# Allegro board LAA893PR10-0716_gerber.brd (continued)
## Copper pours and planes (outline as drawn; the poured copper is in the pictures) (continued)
PBATT+_C on IN2 (solid shape): 62.67,16.67 62.67,11.92 62.59,11.7 62.67,11.47 62.67,9.89 61.86,9.08 61.86,8.14 61.75,8.03 59.11,8.03 58.86,8.28 58.86,9.12 58.86,9.12 58.86,16.72 59.04,16.9 62.44,16.9
PWM1 on BOTTOM (solid shape): 100.06,58.87 100.06,58.65 100.18,58.53 100.5,58.53 100.66,58.37 100.66,57.54 100.6,57.48 99.84,57.48 99.77,57.55 99.77,57.93 99.29,58.41 99.29,58.85 99.42,58.98 99.95,58.98
REGCTL_PNP10 on TOP (solid shape): 252.45,86.34 252.45,86.24 252.52,85.85 252.9,85.76 252.91,85.76 253.13,85.76 253.18,85.71 254.11,85.71 254.17,85.64 254.17,85.53 254.12,85.48 253.09,85.48 253.07,85.45 253.03,85.45 252.94,85.36 251.73,85.36 251.34,84.98 250.43,84.98 250.23,85.17 250.23,86.5 250.49,86.76 252.03,86.76
RING2 on TOP (solid shape): 29.18,18.69 30.6,18.69 30.65,18.64 30.65,18.51 30.6,18.46 27.92,18.46 27.47,18.91 27.47,18.92 25.47,18.92 25.42,18.96 25.42,19.86 25.5,19.94 27.93,19.94
RING2_R on TOP (solid shape): 25.17,20 25.17,19.04 25,18.87 23.09,18.87 22.9,19.05 22.9,19.99 23.05,20.14 25.03,20.14
RING2_R on TOP (solid shape): 15.8,14.95 17.51,14.95 17.73,15.17 18.22,15.17 18.39,15 18.39,14.18 18.23,14.02 17.58,14.02 17.45,13.89 16.5,13.89 16.49,13.91 15.63,13.91 15.62,13.91 14.44,13.91 14.26,14.1 14.26,15.04 14.48,15.25 15.49,15.25
RING2_R on BOTTOM (solid shape): 18.63,15 18.63,14.63 19.09,14.17 20.05,14.17 20.28,13.95 20.28,13.18 20.05,12.95 18.43,12.95 17.61,13.77 17.61,14.96 17.83,15.18 18.45,15.18
RING2_R on IN1 (solid shape): 24.31,19.67 24.31,19.37 23.11,18.17 22.82,18.17 21.96,19.04 21.96,19.18 23.04,20.26 23.72,20.26
RING2_R on IN1 (solid shape): 4.7,15.47 4.7,14.83 5.08,14.45 13.7,14.45 14.41,15.16 14.98,15.16 15.16,14.99 15.16,14.3 14.55,13.69 3.11,13.69 2.79,14.01 2.79,15.4 3.11,15.72 4.44,15.72
RING2_R on IN1 (solid shape): 18.48,14.93 18.48,14.74 18.76,14.46 19.67,14.46 20.05,14.08 20.05,13.39 19.73,13.07 18.12,13.07 17.18,14.01 17.18,14.9 17.46,15.18 18.23,15.18
RING2_R on IN2 (solid shape): 4.7,15.47 4.7,14.83 5.08,14.45 13.73,14.45 14.41,15.14 14.72,15.14 14.86,14.99 14.86,14.05 14.5,13.69 3.11,13.69 2.79,14.01 2.79,15.4 3.11,15.72 4.44,15.72
SLEEVE on TOP (solid shape): 26.9,25.88 27.43,25.88 27.55,25.76 27.55,25.44 27.43,25.32 26.93,25.32 26.83,25.22 25.9,25.22 25.71,25.41 25.71,25.74 25.91,25.93 26.85,25.93
SLEEVE on TOP (solid shape): 25.22,18.43 25.22,17.98 25.44,17.77 27.12,17.77 27.13,17.75 27.55,17.75 27.56,17.77 27.63,17.77 28.2,18.33 29.7,18.33 29.75,18.28 30.59,18.28 30.65,18.22 30.65,18.12 30.6,18.06 29.64,18.06 29.26,17.68 28.75,17.68 28.07,16.99 24.01,16.99 23.91,17.09 23.91,18.47 24.06,18.62 25.03,18.62
SLEEVE on IN1 (solid shape): 25.97,19.52 25.97,18.31 25.38,17.73 24.31,17.73 24.03,18.01 24.03,18.66 25.08,19.71 25.78,19.71
SLEEVE on IN1 (solid shape): 27,25.62 27,24.93 26.28,24.21 25.99,24.21 25.23,24.97 25.23,25.28 25.84,25.89 26.72,25.89
SLEEVE_R on TOP (solid shape): 16.15,25.66 16.15,19.34 16.27,19.23 18.34,19.23 18.64,18.93 22.37,18.93 22.92,18.38 23.56,18.38 23.66,18.27 23.66,17.17 23.58,17.09 23.03,17.09 22.07,17.09 21.79,17.37 20.46,17.37 20.04,17.79 18.48,17.79 18.15,18.12 16.04,18.12 15.67,17.75 14.87,17.75 14.75,17.87 14.75,24.97 14.03,25.69 4.38,25.69 4.06,25.37 4.06,24.61 2.28,24.61 2.28,26.33 3.02,27.06 14.76,27.06
SNB_1.05V on TOP (solid shape): 202.04,56.43 201.79,56.18 200.77,56.18 200.77,57.83 201.41,58.47 201.41,59.1 202.04,59.1
SNUB_1.35V on TOP (solid shape): 65.4,15.79 63.24,15.79 63.12,15.91 63.12,16.93 63.24,17.06 64.01,17.06 64.39,17.44 65.4,17.44
SNUB_3V on TOP (solid shape): 228.02,57.77 228.02,56.16 227.96,56.1 226.38,56.1 226.3,56.18 226.3,57.79 226.68,58.17 227.62,58.17
SNUB_5V on TOP (solid shape): 210.99,54.91 210.8,54.72 209.53,54.72 209.34,54.91 209.34,56.81 210.99,56.81
SW1 on TOP (solid shape): 216.05,49.63 217.24,49.63 217.29,49.58 217.29,49.45 217.24,49.4 216.19,49.4 215.66,48.86 214.42,48.86 214.42,49.78 215.9,49.78
SW1 on TOP (solid shape): 213.61,59.73 213.61,58.23 213.5,58.12 212.56,58.12 212.26,57.83 212.26,56.37 212.52,56.12 214.8,56.12 214.87,56.05 214.87,53.77 214.8,53.7 211.64,53.7 211.31,54.03 211.31,57.83 211.06,58.08 209.53,58.08 209.34,58.27 209.34,59.61 209.6,59.86 213.47,59.86
SW1 on BOTTOM (solid shape): 216.21,58.65 216.21,54.62 215.93,54.34 211.44,54.34 211.25,54.53 211.25,57.39 212.26,57.39 212.26,56.81 212.39,56.69 213.47,56.69 213.6,56.81 213.6,57.39 213.47,57.51 212.39,57.51 212.26,57.39 211.25,57.39 211.25,59.67 211.44,59.86 215,59.86
SW1 on IN1 (solid shape): 215.69,49.89 215.88,49.89 216.07,49.7 216.07,49.32 215.57,48.81 215.31,48.81 214.61,49.51 214.61,50.08 214.8,50.27 215.31,50.27
SW1 on IN1 (solid shape): 212.48,54.7 212.48,53.7 212.34,53.57 211.76,53.57 211.56,53.76 211.56,53.77 211.31,54.02 211.31,54.7 211.45,54.84 212.34,54.84
SW2 on TOP (solid shape): 225.95,58.95 225.95,55.27 226.37,54.84 227.75,54.84 227.99,54.6 227.99,53.49 227.81,53.31 223.96,53.31 223.57,53.71 223.57,56.75 223.3,57.02 223.3,59.07 223.43,59.19 225.71,59.19
SW2 on TOP (solid shape): 222.32,49.75 222.32,48.89 222.3,48.86 221.27,48.86 221.22,48.81 220.96,48.81 220.38,49.4 219.33,49.4 219.26,49.46 219.26,49.56 219.33,49.63 220.52,49.63 220.67,49.78 222.3,49.78
SW2 on BOTTOM (solid shape): 225.41,58.72 225.41,54.32 224.98,53.89 221.54,53.89 221.13,54.3 221.13,58.67 221.42,58.97 225.16,58.97
SW2 on IN1 (solid shape): 225.03,54.34 225.03,53.19 224.01,53.19 224.01,54.34 224.14,54.46 224.9,54.46
SW2 on IN1 (solid shape): 222.25,50.2 222.25,49.82 221.23,48.81 220.72,48.81 220.47,49.06 220.47,49.76 220.72,50.01 221.04,50.01 221.55,50.52 221.93,50.52
SW_1.35V on TOP (solid shape): 68.22,22.43 68.22,21.22 68.36,21.08 68.36,16.14 66.1,13.88 66.1,13.31 66.61,12.8 66.61,12.36 66.48,12.23 66.16,12.23 65.34,13.06 65.34,14.96 66.04,15.66 66.04,21.97 66.61,22.55 68.1,22.55
SW_1.35V on BOTTOM (solid shape): 68.13,22.06 68.13,17.82 67.82,17.5 66.35,17.5 65.47,18.39 64.07,18.39 63.75,18.71 63.75,22.29 63.79,22.33 67.87,22.33
SW_1.35V on BOTTOM (solid shape): 66.46,14.57 66.46,13.96 66.41,13.91 66.27,13.91 66.08,13.72 66.08,13.2 66.69,12.58 66.86,12.58 66.92,12.52 66.92,11.75 66.86,11.69 66.76,11.69 65.34,13.11 65.34,14.53 65.44,14.63 66.39,14.63
SW_+V1.05SP on TOP (solid shape): 204.52,59.77 204.52,56.22 204.43,56.14 203.41,56.14 203.31,56.24 203.31,58 203.06,58.25 203.06,59.73 203.26,59.93 203.31,59.93 204.36,59.93
SW_+V1.05SP on BOTTOM (solid shape): 204.3,60.54 204.3,59.26 204.53,59.03 204.53,56.41 204.29,56.18 201.6,56.18 201.51,56.27 201.51,58.29 202.31,59.1 202.8,59.1 203.12,59.42 203.12,60.56 204.28,60.56
UG_3V on TOP (solid shape): 225.54,59.8 225.54,59.54 225.41,59.42 223.44,59.42 223.31,59.54 223.31,59.86 223.44,59.99 225.35,59.99
UG_3V on TOP (solid shape): 221.03,51.29 221.03,51.04 220.2,50.21 219.33,50.21 219.26,50.27 219.26,50.36 219.37,50.46 219.63,50.46 220.58,51.42 220.9,51.42
UG_3V on IN1 (solid shape): 221.93,51.85 221.93,51.41 221.04,50.52 220.28,50.52 220.09,50.71 220.09,50.96 221.36,52.23 221.55,52.23
UG_3V on IN1 (solid shape): 225.54,59.89 225.54,59.23 225.41,59.1 224.58,59.1 224.2,58.72 223.63,58.72 223.5,58.85 223.5,59.48 224.04,60.02 225.41,60.02
UG_5V on TOP (solid shape): 213.61,57.75 213.61,56.94 213.53,56.87 212.52,56.87 212.44,56.94 212.44,57.63 212.7,57.88 213.48,57.88
UG_5V on TOP (solid shape): 216.93,50.45 217.2,50.45 217.29,50.36 217.29,50.26 217.24,50.21 216.35,50.21 215.62,50.95 215.62,51.33 215.69,51.4 215.97,51.4
UG_5V on IN1 (solid shape): 216.52,50.85 216.52,50.59 216.39,50.46 215.44,50.46 214.68,51.23 214.68,51.61 214.93,51.86 215.5,51.86
UG_5V on IN1 (solid shape): 213.74,57.12 213.74,55.98 212.79,55.98 212.72,56.04 212.72,56.49 212.4,56.81 212.4,57.19 212.6,57.38 213.48,57.38
N18284982 on TOP (solid shape): 64.81,10.13 65.14,10.13 65.23,10.04 65.23,9.79 65.13,9.69 64.71,9.69 64.56,9.54 64.56,9.38 64.5,9.32 63.88,9.32 63.21,8.65 62.36,8.65 62.31,8.71 62.31,9.27 63.21,10.17 64.77,10.17
N18284982 on BOTTOM (solid shape): 66.51,10.23 66.51,10.14 66.45,10.08 65.62,10.08 65.23,9.69 64.82,9.69 64.7,9.81 64.7,10.07 64.8,10.17 64.97,10.16 65.13,10.17 65.26,10.3 66.45,10.3
N18290013 on TOP (solid shape): 105.71,70.71 104.85,69.84 104.85,68.68 104.8,68.63 104.7,68.63 104.64,68.68 104.64,70.39 104.19,70.85 103.55,70.85 103.55,71.48 105.71,71.48
N18292467 on TOP (solid shape): 66.89,91.99 66.89,91.13 66.77,91.01 65.75,91.01 65.62,91.15 65.62,91.94 65.79,92.11 66.77,92.11
N18292467 on TOP (solid shape): 70.07,98.29 70.07,97.46 69.9,97.29 68.63,97.29 68.2,96.86 68.2,96.35 67.99,96.15 67.32,96.15 67.09,96.38 67.09,97.71 67.49,98.11 68.16,98.11 68.51,98.46 69.9,98.46
N18292467 on IN1 (solid shape): 67.4,92.18 67.4,91.83 66.61,91.03 65.71,91.03 65.57,91.17 65.57,91.92 66.38,92.73 66.85,92.73
N18292467 on IN1 (solid shape): 69.97,98.3 69.97,96.74 69.74,96.5 68.76,96.5 68.53,96.74 68.53,97.89 69.07,98.44 69.83,98.44
N18293474 on TOP (solid shape): 74.89,89.1 74.89,88.63 74.54,88.28 74.54,85.67 74.44,85.57 73.02,85.57 72.86,85.73 72.86,88.61 73.49,89.24 74.75,89.24
N18293474 on BOTTOM (solid shape): 75.22,89.09 75.22,87.64 75.11,87.53 73.54,87.53 73.43,87.64 73.43,89.08 73.65,89.31 75.01,89.31
N20364112 on TOP (solid shape): 31.96,14.91 31.96,13.82 30.9,12.76 30.45,12.76 30.31,12.9 30.31,13.21 30.41,13.31 31.04,13.31 31.75,14.02 31.75,14.91 31.81,14.97 31.9,14.97
N20870052 on TOP (solid shape): 67.16,95.94 68,95.94 68.17,95.77 68.17,95.02 67.94,94.79 66.49,94.79 65.92,95.37 65.92,96.11 66.05,96.24 66.85,96.24

Small or netless copper shapes (teardrops, artwork), in the pictures only: 43 on TOP, 257 on BOTTOM

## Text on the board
Ref Des/Silkscreen Bottom: H22 | H19 | REV:A00 | PWA P/N: | PWB P/N:84J8X | COPYRIGHT 2014 | ALL RIGHT RESERVED | LOW VOLTAGE | DDR3L | DIMM A | BT | WLAN | WIGIG
User.Comments: LA-A893P | 2015-07-16 | 2014-07-16 | Win | ZAM60
Ref Des/Silkscreen Top: 1 | 2 | 3 | 4
BODY_CENTER: Width/Space | SB_1_2mm-6L and 8L and 10L (4mil 50ohm )_130801.pdf | VCC | 6 | 4 | 4/4.2 | single 50 | 4/4.5 | single 53 | 3.4/3.5 | 4/6.5 | 90 ohm | 3.4/4.8 | 3.5/9.5 | 3.5/12 | 11/5.3 | no ref
COMPVAL_TYPE_BOTTOM: FIGURE | SIZE | 8.0 | 10.0 | 20.0 | 24.0 | 28.0 | 35.0 | 39.0 | 91.0 | 126.0 | 130.0 | 138.0 | 142.0 | 40.0 | 43.0 | 63.0 | 102.0 | 217.0 | 55.0x24.0 | 55.0x28.0 | 63.0x28.0 | 67.0x28.0 | 67.0x31.0 | 71.0x31.0 | 94.0x28.0 | 100.0x31.0 | 102.0x31.0 | 205.0x102.0 | DRILL CHART: TOP to BOTTOM | ALL UNITS ARE IN MILS | TOLERANCE | +3.0/-3.0 | +2.0/-2.0 | PLATED | NON-PLATED | QTY | 3839 | 518 | 19 | 10 | 27 | 5 | 11 | 1 | 4 | 2 | 3 | 9
User.20: GNDA | +5V_ALW | GND | +3.3V_ALW | +PWR_SRC | +3.3V_RUN | +1.05V_RUN
